(* Logix 5000 project; controller MVI56ADMNETClient 1756-L63 rev 11.1; software revision 11.13 *)
// Example Logic for the MVI56-ADM module.

TASK MainTask (task) : MainProgram

MODULES
   Local : 1756-L63 (rev 11.1)
      ADMNET : vendor 1 type 0 code 15 (rev 1.1, Output RPI 2 ms)
END_MODULES

TYPE ADMModuleDef :
STRUCT
   ReadData : INT[600];
   WriteData : INT[600];
END_STRUCT
END_TYPE

VAR_GLOBAL   (* controller tags *)
   ADM : ADMModuleDef;
   MJFAULTS : DINT[12] := ([0] := -491726278, [1] := 191080, [3] := -495837906, [4] := 191080);
   SendData : BOOL;
   SerialCount : INT := 8;
   SetConnection : BOOL;
END_VAR

PROGRAM MainProgram   (* routine attr 65 MainRoutine *)

ROUTINE MainRoutine   (* ladder *)
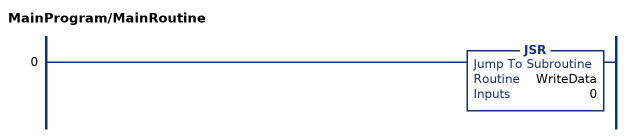
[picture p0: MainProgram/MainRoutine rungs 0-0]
   0: JSR(WriteData,0);
END_ROUTINE

ROUTINE WriteData   (* ladder *)
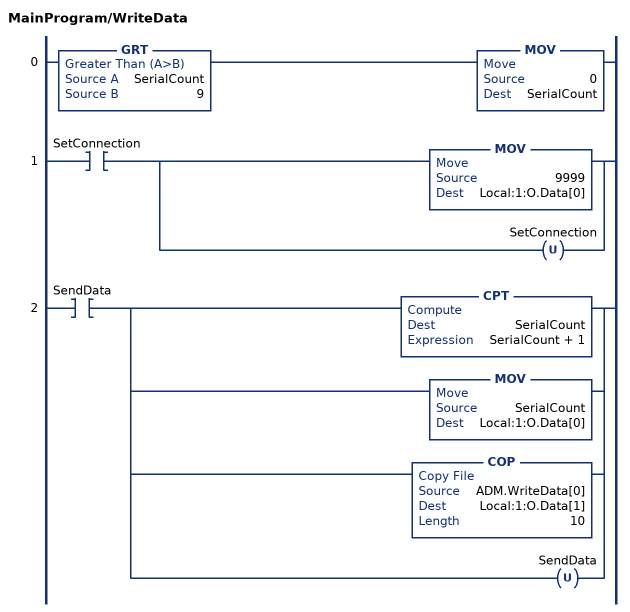
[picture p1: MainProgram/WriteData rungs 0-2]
   0: GRT(SerialCount,9)MOV(0,SerialCount);
   1: XIC(SetConnection)[MOV(9999,Local:1:O.Data[0]) ,OTU(SetConnection) ];
   2: XIC(SendData)[CPT(SerialCount,SerialCount + 1) ,MOV(SerialCount,Local:1:O.Data[0]) ,COP(ADM.WriteData[0],Local:1:O.Data[1],10) ,OTU(SendData) ];
END_ROUTINE
END_PROGRAM

PROGRAM StartUp   (* routine attr 65 PowerUp *)

ROUTINE PowerUp   (* ladder *)
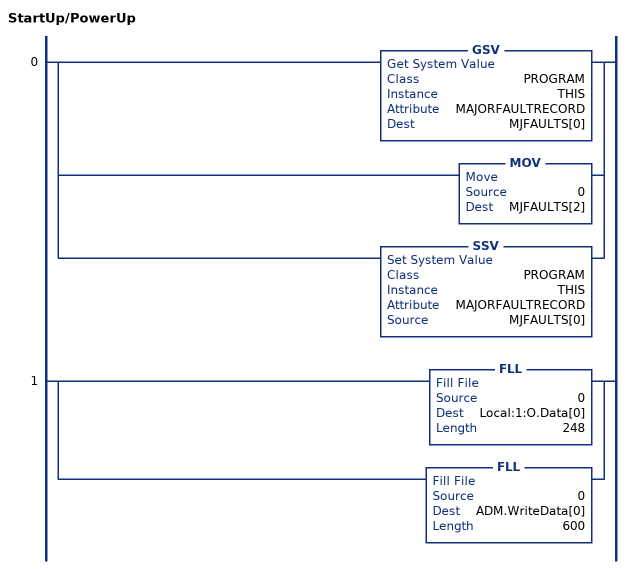
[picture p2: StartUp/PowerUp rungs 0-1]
   0: [GSV(PROGRAM,THIS,MAJORFAULTRECORD,MJFAULTS[0]) ,MOV(0,MJFAULTS[2]) ,SSV(PROGRAM,THIS,MAJORFAULTRECORD,MJFAULTS[0]) ];
   1: [FLL(0,Local:1:O.Data[0],248) ,FLL(0,ADM.WriteData[0],600) ];
END_ROUTINE
END_PROGRAM
